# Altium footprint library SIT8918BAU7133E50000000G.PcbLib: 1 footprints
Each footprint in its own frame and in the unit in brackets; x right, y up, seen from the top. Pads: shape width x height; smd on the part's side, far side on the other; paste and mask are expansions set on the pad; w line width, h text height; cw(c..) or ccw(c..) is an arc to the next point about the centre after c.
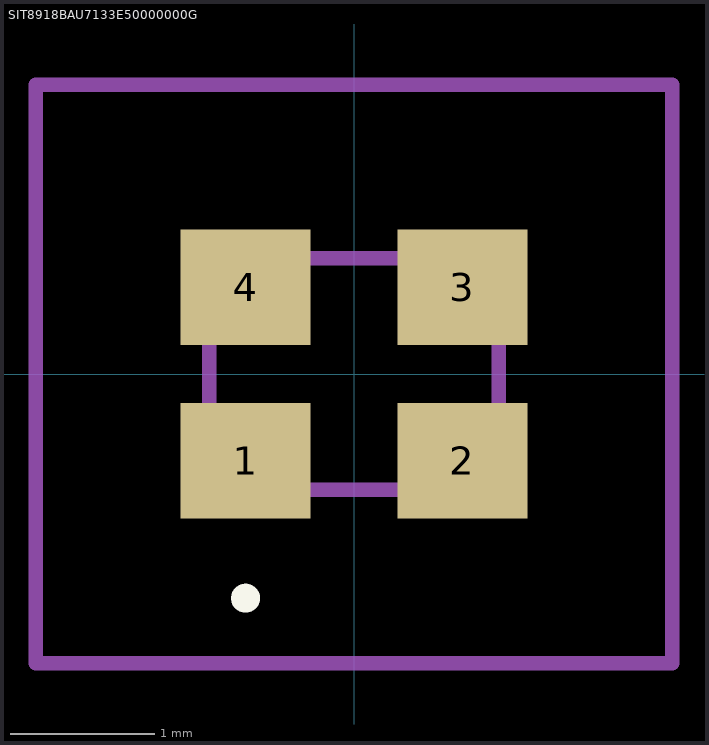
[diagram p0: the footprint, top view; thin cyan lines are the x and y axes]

## SIT8918BAU7133E50000000G [mm]
pads (4):
  rect 0.9x0.8 smd: 1(-0.75,-0.6) 2(0.75,-0.6) 3(0.75,0.6) 4(-0.75,0.6)
Top Overlay:
  lines w0.1: -0.75,-1.6 -0.75,-1.6 ; -0.75,-1.6 ccw(c-0.75,-1.55) -0.75,-1.5 ; -0.75,-1.6 cw(c-0.75,-1.55) -0.75,-1.5 ; -0.75,-1.5 -0.75,-1.5
Mechanical 15:
  lines w0.1: -1,-0.8 1,-0.8 1,0.8 -1,0.8 -1,-0.8
Mechanical 20:
  lines w0.1: -2.2,-2 2.2,-2 2.2,2 -2.2,2 -2.2,-2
